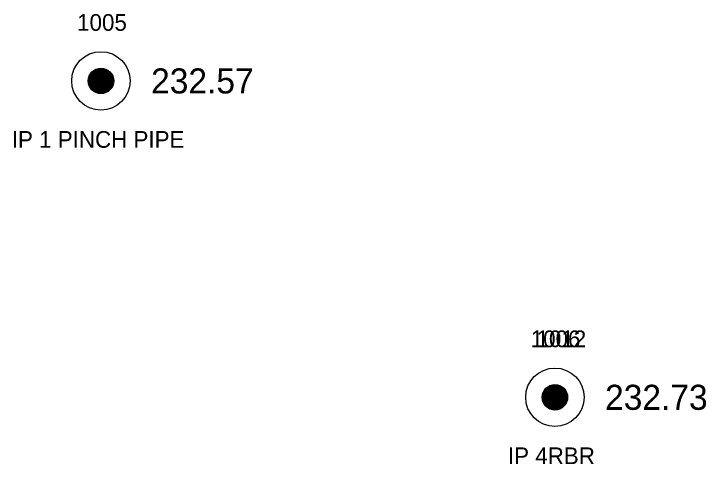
# Model space of a CAD drawing. Extents: x 1961231 to 1962574, y 799865 to 801120.
# Drawn here: x 1962532.54 to 1962573.96, y 800083.43 to 800110.37 of the extents above; entities that cross this region are included whole.
import ezdxf

# ---------------------------------------------------------------- set-up
doc = ezdxf.new("R2010")
doc.units = 0
for name, color, linetype in [('RD_EX_DV_Prop_txCode', 7, 'Continuous'), ('RD_EX_DV_PropPin', 7, 'Continuous'), ('RD_EX_TX_DV_Prop_ELEV', 7, 'Continuous'), ('RD_SMD_Locator', 7, 'Continuous')]:
    doc.layers.add(name, color=color, linetype=linetype)

msp = doc.modelspace()

# ---------------------------------------------------------------- linework, layer by layer
at = {"layer": 'RD_EX_DV_PropPin'}
for p, q in [((1962537.227, 800105.806), (1962537.227, 800106.908)), ((1962537.262, 800105.775), (1962537.262, 800106.939)), ((1962537.297, 800105.747), (1962537.297, 800106.967)), ((1962537.332, 800105.723), (1962537.332, 800106.992)), ((1962537.367, 800105.701), (1962537.367, 800107.014)), ((1962537.402, 800105.682), (1962537.402, 800107.033)), ((1962537.437, 800105.664), (1962537.437, 800107.05)), ((1962537.472, 800105.65), (1962537.472, 800107.065)), ((1962537.507, 800105.637), (1962537.507, 800107.078)), ((1962537.542, 800105.626), (1962537.542, 800107.089)), ((1962537.577, 800105.617), (1962537.577, 800107.098)), ((1962537.612, 800105.609), (1962537.612, 800107.105)), ((1962537.647, 800105.603), (1962537.647, 800107.111)), ((1962537.682, 800105.599), (1962537.682, 800107.115)), ((1962537.717, 800105.597), (1962537.717, 800107.117)), ((1962537.752, 800105.596), (1962537.752, 800107.118)), ((1962537.787, 800105.597), (1962537.787, 800107.117)), ((1962537.823, 800105.599), (1962537.823, 800107.115)), ((1962537.858, 800105.603), (1962537.858, 800107.111)), ((1962537.893, 800105.609), (1962537.893, 800107.105)), ((1962537.928, 800105.617), (1962537.928, 800107.098)), ((1962537.963, 800105.626), (1962537.963, 800107.089)), ((1962537.998, 800105.637), (1962537.998, 800107.078)), ((1962538.033, 800105.65), (1962538.033, 800107.065)), ((1962538.068, 800105.664), (1962538.068, 800107.05)), ((1962538.103, 800105.682), (1962538.103, 800107.033)), ((1962538.138, 800105.701), (1962538.138, 800107.014)), ((1962538.173, 800105.723), (1962538.173, 800106.992)), ((1962538.208, 800105.747), (1962538.208, 800106.967)), ((1962538.243, 800105.775), (1962538.243, 800106.939)), ((1962538.278, 800105.806), (1962538.278, 800106.908)), ((1962537.017, 800106.161), (1962537.017, 800106.553)), ((1962537.052, 800106.059), (1962537.052, 800106.655)), ((1962537.087, 800105.988), (1962537.087, 800106.727)), ((1962537.122, 800105.931), (1962537.122, 800106.784)), ((1962537.157, 800105.883), (1962537.157, 800106.831)), ((1962537.192, 800105.842), (1962537.192, 800106.872)), ((1962538.313, 800105.842), (1962538.313, 800106.872)), ((1962538.348, 800105.883), (1962538.348, 800106.831)), ((1962538.383, 800105.931), (1962538.383, 800106.784)), ((1962538.418, 800105.988), (1962538.418, 800106.727)), ((1962538.453, 800106.059), (1962538.453, 800106.655)), ((1962538.488, 800106.161), (1962538.488, 800106.553)), ((1962564.281, 800087), (1962564.281, 800087.853)), ((1962564.281, 800087), (1962564.281, 800087.853)), ((1962564.316, 800086.953), (1962564.316, 800087.901)), ((1962564.316, 800086.953), (1962564.316, 800087.901)), ((1962564.351, 800086.912), (1962564.351, 800087.942)), ((1962564.351, 800086.912), (1962564.351, 800087.942)), ((1962564.386, 800086.876), (1962564.386, 800087.978)), ((1962564.386, 800086.876), (1962564.386, 800087.978)), ((1962564.421, 800086.845), (1962564.421, 800088.009)), ((1962564.421, 800086.845), (1962564.421, 800088.009)), ((1962564.456, 800086.817), (1962564.456, 800088.037)), ((1962564.456, 800086.817), (1962564.456, 800088.037)), ((1962564.491, 800086.792), (1962564.491, 800088.061)), ((1962564.491, 800086.792), (1962564.491, 800088.061)), ((1962564.526, 800086.77), (1962564.526, 800088.083)), ((1962564.526, 800086.77), (1962564.526, 800088.083)), ((1962564.561, 800086.751), (1962564.561, 800088.102)), ((1962564.561, 800086.751), (1962564.561, 800088.102)), ((1962564.596, 800086.734), (1962564.596, 800088.12)), ((1962564.596, 800086.734), (1962564.596, 800088.12)), ((1962564.631, 800086.719), (1962564.631, 800088.134)), ((1962564.631, 800086.719), (1962564.631, 800088.134)), ((1962564.666, 800086.706), (1962564.666, 800088.147)), ((1962564.666, 800086.706), (1962564.666, 800088.147)), ((1962564.701, 800086.695), (1962564.701, 800088.158)), ((1962564.701, 800086.695), (1962564.701, 800088.158)), ((1962564.736, 800086.686), (1962564.736, 800088.167)), ((1962564.736, 800086.686), (1962564.736, 800088.167)), ((1962564.771, 800086.679), (1962564.771, 800088.175)), ((1962564.771, 800086.679), (1962564.771, 800088.175)), ((1962564.806, 800086.673), (1962564.806, 800088.181)), ((1962564.806, 800086.673), (1962564.806, 800088.181)), ((1962564.841, 800086.669), (1962564.841, 800088.185)), ((1962564.841, 800086.669), (1962564.841, 800088.185)), ((1962564.876, 800086.667), (1962564.876, 800088.187)), ((1962564.876, 800086.667), (1962564.876, 800088.187)), ((1962564.911, 800086.666), (1962564.911, 800088.188)), ((1962564.911, 800086.666), (1962564.911, 800088.188)), ((1962564.946, 800086.667), (1962564.946, 800088.187)), ((1962564.946, 800086.667), (1962564.946, 800088.187)), ((1962564.981, 800086.669), (1962564.981, 800088.185)), ((1962564.981, 800086.669), (1962564.981, 800088.185)), ((1962565.016, 800086.673), (1962565.016, 800088.181)), ((1962565.016, 800086.673), (1962565.016, 800088.181)), ((1962565.051, 800086.679), (1962565.051, 800088.175)), ((1962565.051, 800086.679), (1962565.051, 800088.175)), ((1962565.086, 800086.686), (1962565.086, 800088.167)), ((1962565.086, 800086.686), (1962565.086, 800088.167)), ((1962565.121, 800086.695), (1962565.121, 800088.158)), ((1962565.121, 800086.695), (1962565.121, 800088.158)), ((1962565.156, 800086.706), (1962565.156, 800088.147)), ((1962565.156, 800086.706), (1962565.156, 800088.147)), ((1962565.191, 800086.719), (1962565.191, 800088.134)), ((1962565.191, 800086.719), (1962565.191, 800088.134)), ((1962565.226, 800086.734), (1962565.226, 800088.12)), ((1962565.226, 800086.734), (1962565.226, 800088.12)), ((1962565.261, 800086.751), (1962565.261, 800088.102)), ((1962565.261, 800086.751), (1962565.261, 800088.102)), ((1962565.296, 800086.77), (1962565.296, 800088.083)), ((1962565.296, 800086.77), (1962565.296, 800088.083)), ((1962565.331, 800086.792), (1962565.331, 800088.061)), ((1962565.331, 800086.792), (1962565.331, 800088.061)), ((1962565.366, 800086.817), (1962565.366, 800088.037)), ((1962565.366, 800086.817), (1962565.366, 800088.037)), ((1962565.401, 800086.845), (1962565.401, 800088.009)), ((1962565.401, 800086.845), (1962565.401, 800088.009)), ((1962565.436, 800086.876), (1962565.436, 800087.978)), ((1962565.436, 800086.876), (1962565.436, 800087.978)), ((1962565.471, 800086.912), (1962565.471, 800087.942)), ((1962565.471, 800086.912), (1962565.471, 800087.942)), ((1962565.506, 800086.953), (1962565.506, 800087.901)), ((1962565.506, 800086.953), (1962565.506, 800087.901)), ((1962565.541, 800087), (1962565.541, 800087.853)), ((1962565.541, 800087), (1962565.541, 800087.853)), ((1962564.175, 800087.231), (1962564.175, 800087.623)), ((1962564.175, 800087.231), (1962564.175, 800087.623)), ((1962564.21, 800087.129), (1962564.21, 800087.725)), ((1962564.21, 800087.129), (1962564.21, 800087.725)), ((1962564.246, 800087.057), (1962564.246, 800087.796)), ((1962564.246, 800087.057), (1962564.246, 800087.796)), ((1962565.576, 800087.057), (1962565.576, 800087.796)), ((1962565.576, 800087.057), (1962565.576, 800087.796)), ((1962565.611, 800087.129), (1962565.611, 800087.725)), ((1962565.611, 800087.129), (1962565.611, 800087.725)), ((1962565.646, 800087.231), (1962565.646, 800087.623)), ((1962565.646, 800087.231), (1962565.646, 800087.623))]:
    msp.add_line(p, q, dxfattribs=at)
for centre, radius in [((1962537.752, 800106.357), 1.75), ((1962537.752, 800106.357), 0.761), ((1962564.911, 800087.427), 1.75), ((1962564.911, 800087.427), 1.75), ((1962564.911, 800087.427), 0.761), ((1962564.911, 800087.427), 0.761)]:
    msp.add_circle(centre, radius, dxfattribs=at)
at = {"layer": 'RD_SMD_Locator'}
for centre in [(1962537.753, 800106.357), (1962564.911, 800087.427), (1962564.911, 800087.427)]:
    msp.add_circle(centre, 0.15, dxfattribs=at)

# ---------------------------------------------------------------- texts
at = {"layer": 'RD_EX_DV_Prop_txCode'}
for s, p in [('1005', (1962536.327, 800109.357)), ('IP 1 PINCH PIPE', (1962532.418, 800102.357)), ('1006', (1962563.462, 800090.427)), ('1012', (1962563.808, 800090.427)), ('IP 4RBR', (1962562.1, 800083.427)), ('IP 4RBR', (1962562.1, 800083.427))]:
    msp.add_text(s, height=1, dxfattribs=at).set_placement(p)
at = {"layer": 'RD_EX_TX_DV_Prop_ELEV'}
for s, p in [('232.57', (1962540.753, 800105.607)), ('232.73', (1962567.911, 800086.677)), ('232.73', (1962567.911, 800086.677))]:
    msp.add_text(s, height=1.5, dxfattribs=at).set_placement(p)

doc.saveas('drawing.dxf')
